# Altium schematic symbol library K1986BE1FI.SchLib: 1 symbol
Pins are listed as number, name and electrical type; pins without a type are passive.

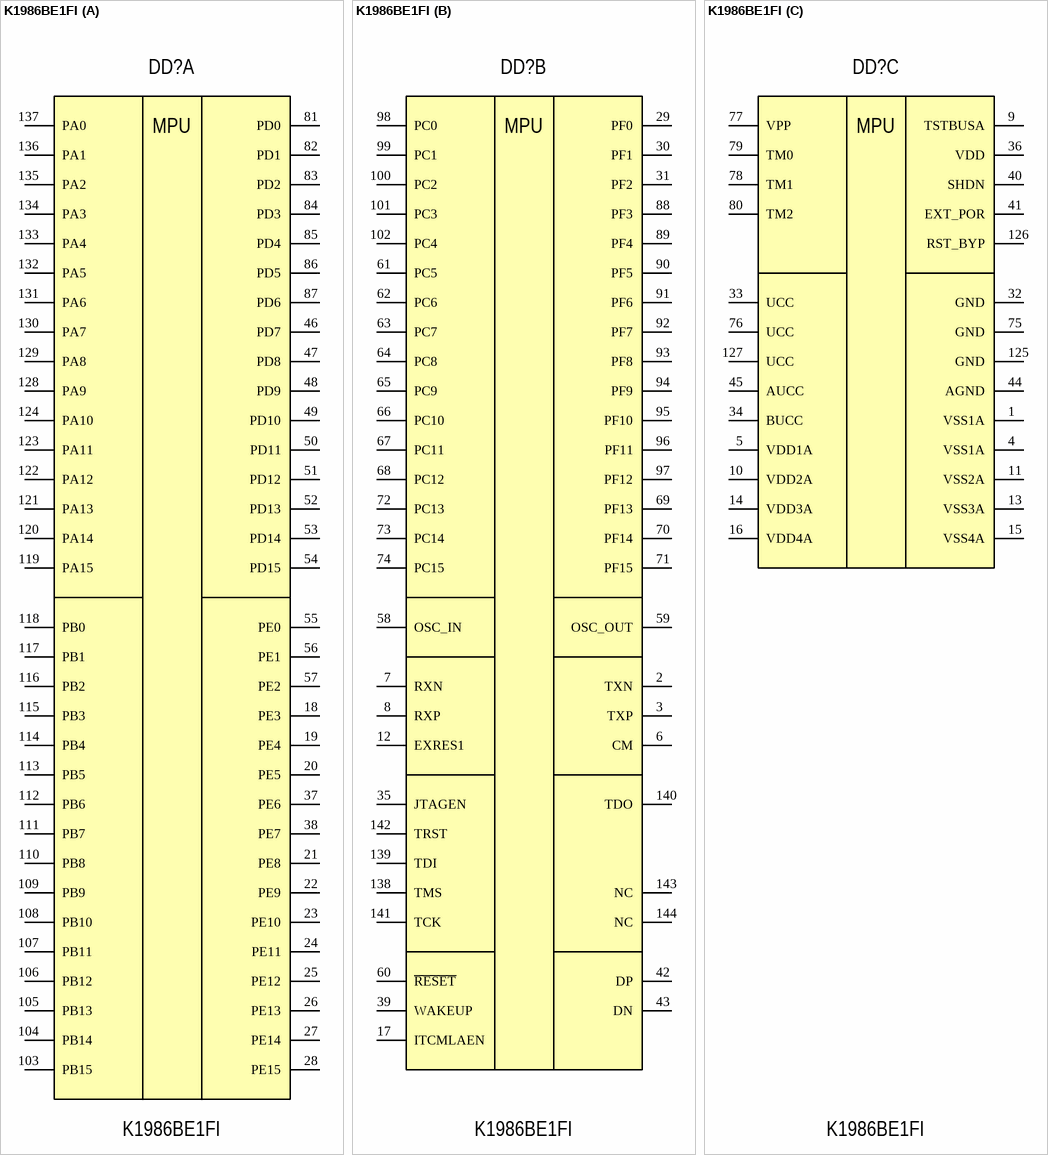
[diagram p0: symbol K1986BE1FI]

## K1986BE1FI
designator DD?
Микросхема 32-разрядной микро-ЭВМ с Ethernet интерфейсом; Vendor Code: K1986BE1FI ТСКЯ.431000.001ТУ; Vendor: ООО "Миландр ЭК"; Data Sheet: ТСКЯ.430109.006ГЧ
footprint К1986ВЕ1FI (Package Type - QFN144 22x22x1,6 (0,5))
part A pins: 18 PE3, 19 PE4, 20 PE5, 21 PE8, 22 PE9, 23 PE10, 24 PE11, 25 PE12, 26 PE13, 27 PE14, 28 PE15, 37 PE6, 38 PE7, 46 PD7, 47 PD8, 48 PD9, 49 PD10, 50 PD11, 51 PD12, 52 PD13, 53 PD14, 54 PD15, 55 PE0, 56 PE1, 57 PE2, 81 PD0, 82 PD1, 83 PD2, 84 PD3, 85 PD4, 86 PD5, 87 PD6, 103 PB15, 104 PB14, 105 PB13, 106 PB12, 107 PB11, 108 PB10, 109 PB9, 110 PB8, 111 PB7, 112 PB6, 113 PB5, 114 PB4, 115 PB3, 116 PB2, 117 PB1, 118 PB0, 119 PA15, 120 PA14, 121 PA13, 122 PA12, 123 PA11, 124 PA10, 128 PA9, 129 PA8, 130 PA7, 131 PA6, 132 PA5, 133 PA4, 134 PA3, 135 PA2, 136 PA1, 137 PA0
part B pins: 2 TXN, 3 TXP, 6 CM, 7 RXN, 8 RXP, 12 EXRES1, 17 ITCMLAEN, 29 PF0, 30 PF1, 31 PF2, 35 JTAGEN, 39 WAKEUP, 42 DP, 43 DN, 58 OSC_IN, 59 OSC_OUT, 60 ~{RESET}, 61 PC5, 62 PC6, 63 PC7, 64 PC8, 65 PC9, 66 PC10, 67 PC11, 68 PC12, 69 PF13, 70 PF14, 71 PF15, 72 PC13, 73 PC14, 74 PC15, 88 PF3, 89 PF4, 90 PF5, 91 PF6, 92 PF7, 93 PF8, 94 PF9, 95 PF10, 96 PF11, 97 PF12, 98 PC0, 99 PC1, 100 PC2, 101 PC3, 102 PC4, 138 TMS, 139 TDI, 140 TDO, 141 TCK, 142 TRST, 143 NC, 144 NC
part C pins: 1 VSS1A, 4 VSS1A, 5 VDD1A, 9 TSTBUSA, 10 VDD2A, 11 VSS2A, 13 VSS3A, 14 VDD3A, 15 VSS4A, 16 VDD4A, 32 GND, 33 UCC, 34 BUCC, 36 VDD, 40 SHDN, 41 EXT_POR, 44 AGND, 45 AUCC, 75 GND, 76 UCC, 77 VPP, 78 TM1, 79 TM0, 80 TM2, 125 GND, 126 RST_BYP, 127 UCC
